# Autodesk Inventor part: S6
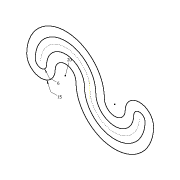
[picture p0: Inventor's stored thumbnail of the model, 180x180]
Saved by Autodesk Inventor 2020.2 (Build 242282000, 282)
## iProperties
Created: 2013-12
Part Number: S6
Material: Ogólny
Document SubType Name: Modeling
Designer: F.Stasiak
Density: 1 g/cm^3
Appearance: Domyślna
Manager: www.cadconsulting.pl
Company: Fabian Stasiak CAD Consulting
Author: F.Stasiak
Subject: Zbiór ćwiczeń. Autodesk Inventor 2020. Kurs podstawowy
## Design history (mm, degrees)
sketch "Szkic1"
  geometry: L1 (0, -9.017)-(0, 9.008) reference; A1 r 26 centre (-26, 0) between (0, 0) and (-52, 0); A2 r 32 centre (-26, 0) between (6, 0) and (-58, 0); A3 r 20 centre (-26, 0) between (-6, 0) and (-46, 0); A4 r 6 centre (-52, 0) between (-58, 0) and (-46, 0); A5 r 26 centre (26, 0) between (0, 0) and (52, 0); A6 r 32 centre (26, 0) between (-6, 0) and (58, 0); A7 r 20 centre (26, 0) between (6, 0) and (46, 0); A8 r 6 centre (52, 0) between (58, 0) and (46, 0); A9 r 41 centre (-26, 0) between (15, 0) and (-67, 0); A10 r 11 centre (26, 0) between (15, 0) and (37, 0); A11 r 15 centre (52, 0) between (67, 0) and (37, 0); A12 r 41 centre (26, 0) between (-15, 0) and (67, 0); A13 r 11 centre (-26, 0) between (-15, 0) and (-37, 0); A14 r 15 centre (-52, 0) between (-67, 0) and (-37, 0)
  constraints: 28 point on circle, 14 centre point, 5 tangent, 2 horizontal alignment, 1 equal radius, 9 other
  dimensions: "d0" = 20 radius of A3; "d1" = 6 radius of A4; "d2" = 15 radius of A14
